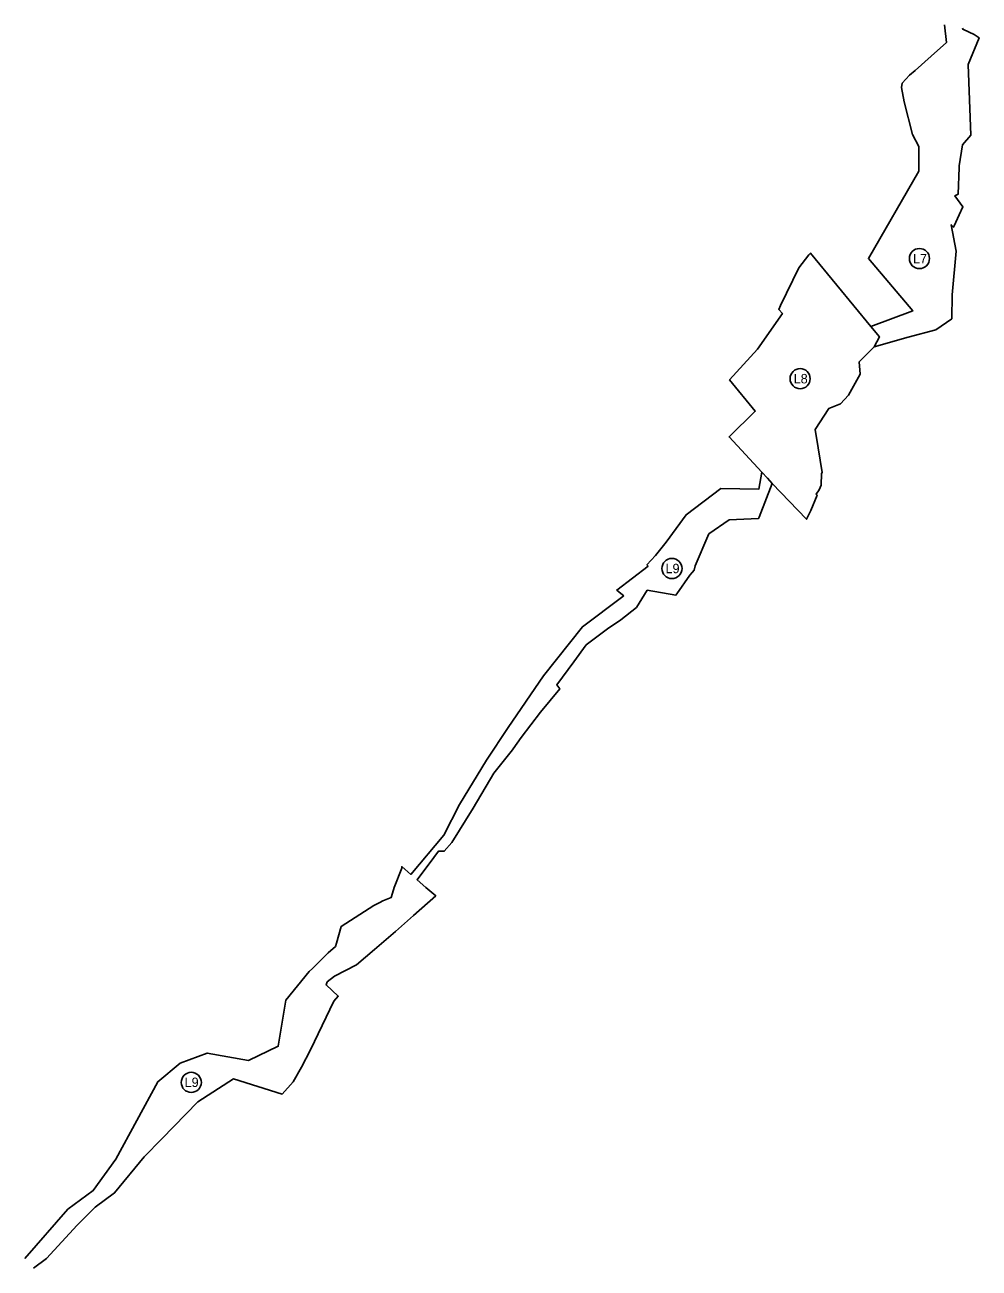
# Model space of a CAD drawing. Extents: x -445081 to -429827, y -1135509 to -1130103.
# Drawn here: x -443448 to -442234, y -1131685 to -1130103 of the extents above; entities that cross this region are included whole.
import ezdxf

# ---------------------------------------------------------------- set-up
doc = ezdxf.new("R2010")
doc.units = 0
for name, color, linetype in [('Vrstva 32', 7, 'Continuous'), ('Vrstva 33', 7, 'Continuous'), ('Vrstva 36', 7, 'Continuous')]:
    doc.layers.add(name, color=color, linetype=linetype)

msp = doc.modelspace()

# ---------------------------------------------------------------- linework, layer by layer
at = {"layer": 'Vrstva 32'}
for points in [[(-442503.2, -1130679.4), (-442497.1, -1130686.2), (-442453.5, -1130731.8), (-442447.9, -1130720.6), (-442440.1, -1130700.9), (-442441.5, -1130699.9), (-442437.6, -1130694.2), (-442435.1, -1130688.2), (-442434.7, -1130673.7), (-442433.7, -1130672.4), (-442438.8, -1130641.1), (-442442.7, -1130617.4), (-442425.1, -1130590.7), (-442410.4, -1130584.7), (-442400.3, -1130573.9), (-442385.2, -1130547.3), (-442386.5, -1130531.4), (-442367.7, -1130512.3), (-442360.8, -1130499.6), (-442371.6, -1130486.5), (-442414.9, -1130434), (-442448.7, -1130393.1), (-442450.5, -1130395.2), (-442463.4, -1130411.9), (-442486.8, -1130460), (-442488.8, -1130464.7), (-442484.2, -1130470), (-442515.7, -1130515.5), (-442551.5, -1130554.4), (-442518.7, -1130594.4), (-442552, -1130627.1), (-442510.3, -1130671.8), (-442503.2, -1130679.4)], [(-442497.1, -1130686.2), (-442453.5, -1130731.8), (-442447.9, -1130720.6), (-442440.1, -1130700.9), (-442441.5, -1130699.9), (-442437.6, -1130694.2), (-442435.1, -1130688.2), (-442434.7, -1130673.7), (-442434.7, -1130673.7), (-442433.7, -1130672.4), (-442438.8, -1130641.1), (-442442.7, -1130617.4), (-442442.7, -1130617.4), (-442425.1, -1130590.7), (-442410.4, -1130584.7), (-442400.3, -1130573.9), (-442400.3, -1130573.9), (-442385.2, -1130547.3), (-442385.2, -1130547.3), (-442386.5, -1130531.4), (-442367.7, -1130512.3), (-442360.8, -1130499.6), (-442371.6, -1130486.5), (-442414.9, -1130434), (-442448.7, -1130393.1), (-442450.5, -1130395.2), (-442463.4, -1130411.9), (-442463.4, -1130411.9), (-442486.8, -1130460), (-442488.8, -1130464.7), (-442484.2, -1130470), (-442515.7, -1130515.5), (-442551.5, -1130554.4), (-442518.7, -1130594.4), (-442552, -1130627.1), (-442510.3, -1130671.8), (-442503.2, -1130679.4), (-442497.1, -1130686.2)]]:
    msp.add_lwpolyline(points, dxfattribs=at)
at = {"layer": 'Vrstva 33'}
for points in [[(-442371.6, -1130486.5), (-442318.4, -1130466.6), (-442374.8, -1130400.1), (-442310.9, -1130289), (-442310.9, -1130257.4), (-442318.8, -1130242.4), (-442329.2, -1130200.7), (-442332.8, -1130182.5), (-442331.8, -1130176.9), (-442322.7, -1130166.6), (-442315.4, -1130161), (-442294.9, -1130142.6), (-442275.7, -1130125.1), (-442277.9, -1130102.8)], [(-442255.1, -1130106.9), (-442254.8, -1130108.2), (-442246.8, -1130112), (-442240.2, -1130115.2), (-442234.1, -1130119.1), (-442248.1, -1130153), (-442244.5, -1130243), (-442255.2, -1130255.3), (-442259.6, -1130282), (-442259.6, -1130284.4), (-442260.9, -1130318.2), (-442264.8, -1130320.2), (-442254.7, -1130334.1), (-442259.4, -1130344.3), (-442265.6, -1130358.6), (-442266.8, -1130360.2), (-442269.5, -1130357.1), (-442263.4, -1130390.5), (-442268.2, -1130446.1), (-442268.2, -1130446.1), (-442268.2, -1130446.1), (-442268.8, -1130476.7), (-442289.2, -1130490.6), (-442324.2, -1130500.2), (-442367.7, -1130512.3)], [(-442686.1, -1130829.2), (-442691.7, -1130824.5), (-442694.9, -1130821.8), (-442655, -1130791.3), (-442656.5, -1130789.8), (-442645.8, -1130777.9), (-442632, -1130760.9), (-442606.7, -1130726), (-442562.7, -1130692.5), (-442514.2, -1130693.4), (-442510.3, -1130671.8)], [(-442497.1, -1130686.2), (-442513.9, -1130729.1), (-442514.5, -1130730.6), (-442551.9, -1130732.3), (-442577.9, -1130750.5), (-442595.2, -1130791.2), (-442596.6, -1130796.5), (-442598.9, -1130799.3), (-442601.8, -1130802.7), (-442618.4, -1130826.5), (-442619.6, -1130828.2), (-442656.1, -1130822), (-442669.8, -1130844.1)], [(-443447.6, -1131672.1), (-443392.9, -1131609.3), (-443360.7, -1131585.8), (-443331.8, -1131546.1), (-443278.6, -1131447.3), (-443250.2, -1131423.9), (-443215.8, -1131410.9), (-443163.2, -1131420.4), (-443125.3, -1131402.3), (-443115.7, -1131343.5), (-443086.1, -1131307.1), (-443081.9, -1131303.5), (-443062, -1131283.2), (-443052.7, -1131275.2), (-443051.5, -1131270.9), (-443045.6, -1131250), (-443003.9, -1131223), (-442996.3, -1131219.2), (-442992.4, -1131217.4), (-442981.8, -1131212.9), (-442978.9, -1131203.2), (-442977.8, -1131200.2), (-442968.4, -1131175.7), (-442968.3, -1131173.7), (-442968.3, -1131173.7), (-442956.8, -1131183.6), (-442914.7, -1131133.7), (-442894.7, -1131094.7), (-442860.4, -1131038.3), (-442833, -1130996.7), (-442787.9, -1130930.9), (-442738.6, -1130868.5), (-442687, -1130829.9), (-442686.1, -1130829.2)], [(-442669.8, -1130844.1), (-442689.6, -1130859.9), (-442706.6, -1130871.1), (-442733.7, -1130891.4), (-442749.3, -1130913.3), (-442771.2, -1130942.4), (-442767.5, -1130947.5), (-442791.8, -1130977.1), (-442816.5, -1131009.6), (-442826.6, -1131023.7), (-442827.7, -1131025.3), (-442851.1, -1131054.7), (-442877.4, -1131099.5), (-442904.6, -1131143.2), (-442914.2, -1131154.1), (-442921.7, -1131154.1), (-442927.7, -1131161.9), (-442948.9, -1131190.3), (-442937.6, -1131200.1), (-442925, -1131210.8), (-442953.6, -1131236), (-442976.4, -1131256.1), (-443002.8, -1131279.1), (-443025.7, -1131298.8), (-443054, -1131312.9), (-443063.4, -1131320.3)], [(-443063.4, -1131320.3), (-443064.6, -1131324.3), (-443049.2, -1131338.5), (-443054.9, -1131345), (-443084.2, -1131406.8), (-443095.8, -1131428.9), (-443106.5, -1131447.3), (-443120.3, -1131463), (-443182.5, -1131443.5), (-443227.7, -1131473.1), (-443273.6, -1131519.9), (-443295.8, -1131542.9), (-443333.6, -1131588.9), (-443358.2, -1131607), (-443381.2, -1131630), (-443420.3, -1131672.4), (-443436.5, -1131684.5)]]:
    msp.add_lwpolyline(points, dxfattribs=at)
at = {"layer": 'Vrstva 36'}
for centre in [(-442310, -1130400.1), (-442461.7, -1130552.9), (-442624.7, -1130794.4), (-443236, -1131448.2)]:
    msp.add_circle(centre, 12.8, dxfattribs=at)

# ---------------------------------------------------------------- texts
for s, p in [('L7', (-442318.2, -1130406.1)), ('L8', (-442469.9, -1130558.9)), ('L9', (-442632.9, -1130800.4)), ('L9', (-443244.5, -1131454.1))]:
    msp.add_text(s, height=12, dxfattribs=at).set_placement(p)

doc.saveas('drawing.dxf')
